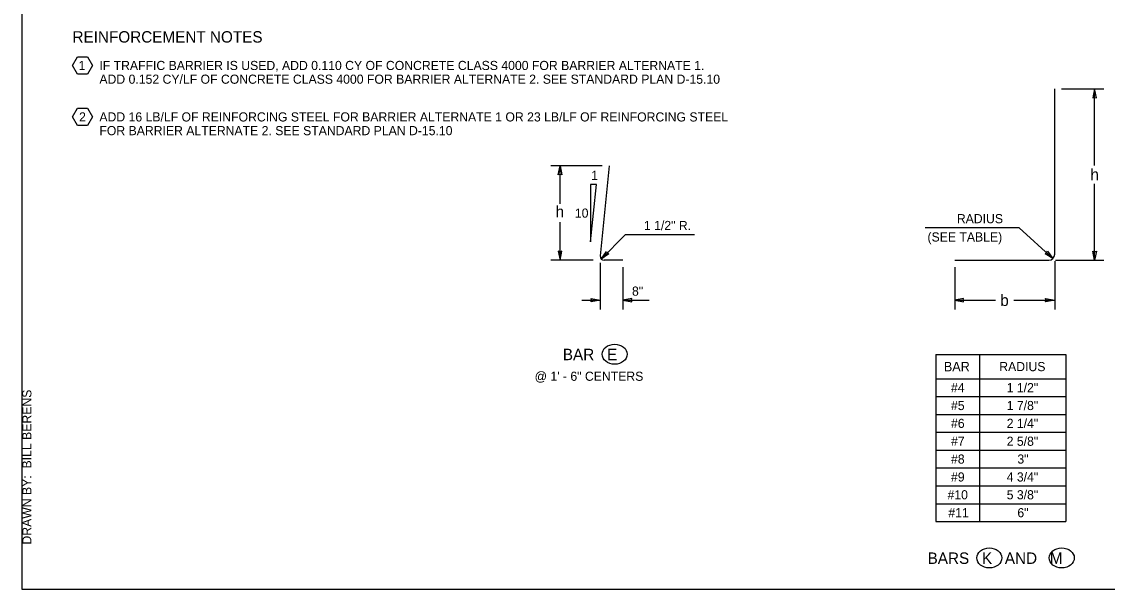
# Model space of a CAD drawing. Extents: x 99862 to 103151, y 100000 to 105076.
# Drawn here: x 99862 to 101763, y 103000 to 103992 of the extents above; entities that cross this region are included whole.
import ezdxf

# ---------------------------------------------------------------- set-up
doc = ezdxf.new("R2010")
doc.units = 0
for name, color, linetype in [('Level 1', 7, 'Continuous'), ('Level 15', 7, 'Continuous'), ('Level 20', 7, 'Continuous'), ('Level 21', 7, 'Continuous'), ('Level 4', 7, 'Continuous'), ('Level 5', 7, 'Continuous'), ('Level 60', 7, 'Continuous'), ('Level 62', 7, 'Continuous')]:
    doc.layers.add(name, color=color, linetype=linetype)

msp = doc.modelspace()

# ---------------------------------------------------------------- linework, layer by layer
at = {"layer": 'Level 1'}
msp.add_lwpolyline([(99862, 102999.5), (103151, 102999.5), (103151, 105075.5), (99862, 105075.5)], close=True, dxfattribs=at)
at = {"layer": 'Level 15'}
for p, q in [((101682.7, 103875.1), (101756.7, 103875.1)), ((101740.7, 103741.1), (101740.7, 103875.1)), ((100878.3, 103740.1), (100788.6, 103740.1)), ((100804.6, 103673.6), (100804.6, 103740.1)), ((100868.2, 103707.6), (100858.2, 103707.6)), ((100858.2, 103707.6), (100858.2, 103607.6)), ((100858.2, 103607.6), (100868.2, 103707.6)), ((101740.7, 103575.1), (101740.7, 103709.1)), ((100804.6, 103575.1), (100804.6, 103641.6)), ((100919.5, 103620), (100876.8, 103577.3)), ((100919.5, 103620), (101040.1, 103620)), ((101608.3, 103631.9), (101444.2, 103631.9)), ((101608.3, 103631.9), (101667.6, 103578.2)), ((100862.6, 103575.1), (100788.6, 103575.1)), ((100874.6, 103570.6), (100874.6, 103489.1)), ((100914.6, 103563.1), (100914.6, 103489.1)), ((101495.6, 103563.1), (101495.6, 103489.1)), ((101670.7, 103573.6), (101670.7, 103489.1)), ((101672.2, 103575.1), (101756.7, 103575.1)), ((100842.6, 103505.1), (100874.6, 103505.1)), ((100914.6, 103505.1), (100960.4, 103505.1)), ((101495.6, 103505.1), (101567.1, 103505.1)), ((101599.1, 103505.1), (101670.7, 103505.1))]:
    msp.add_line(p, q, dxfattribs=at)
for points in [[(101740.7, 103875.1), (101737.6, 103859.4), (101740.7, 103860.1), (101743.8, 103859.4)], [(101740.7, 103875.1), (101739.1, 103867.3), (101740.7, 103867.6), (101742.2, 103867.3)], [(100804.6, 103740.1), (100807.7, 103724.4), (100804.6, 103725.1), (100801.5, 103724.4)], [(100804.6, 103575.1), (100807.7, 103590.9), (100804.6, 103590.1), (100801.5, 103590.9)], [(100876.8, 103577.3), (100885.8, 103590.6), (100887.4, 103587.9), (100890.1, 103586.3)], [(101667.6, 103578.2), (101653.9, 103586.5), (101656.5, 103588.3), (101658, 103591)], [(101740.7, 103575.1), (101737.6, 103590.9), (101740.7, 103590.1), (101743.8, 103590.9)], [(101740.7, 103575.1), (101739.1, 103583), (101740.7, 103582.6), (101742.2, 103583)], [(100874.6, 103505.1), (100858.9, 103502.1), (100859.6, 103505.1), (100858.9, 103508.2)], [(100914.6, 103505.1), (100930.3, 103502.1), (100929.6, 103505.1), (100930.3, 103508.2)], [(101495.6, 103505.1), (101511.3, 103502.1), (101510.6, 103505.1), (101511.3, 103508.2)], [(101670.7, 103505.1), (101654.9, 103502.1), (101655.7, 103505.1), (101654.9, 103508.2)]]:
    msp.add_lwpolyline(points, close=True, dxfattribs=at)
at = {"layer": 'Level 20'}
for points in [[(99951.2, 103915.9), (99959.8, 103930.9), (99977.1, 103930.9), (99985.8, 103915.9), (99977.1, 103900.9), (99959.8, 103900.9), (99951.2, 103915.9)], [(99951.2, 103825.9), (99959.8, 103840.9), (99977.1, 103840.9), (99985.8, 103825.9), (99977.1, 103810.9), (99959.8, 103810.9), (99951.2, 103825.9)]]:
    msp.add_lwpolyline(points, dxfattribs=at)
for centre in [(100900.2, 103410.7), (101556.3, 103054.3), (101683.2, 103054.3)]:
    msp.add_ellipse(centre, major_axis=(-21.9, 0), ratio=0.8, dxfattribs=at)
at = {"layer": 'Level 4'}
for p, q in [((101462.5, 103410.3), (101690.5, 103410.3)), ((101462.5, 103410.3), (101462.5, 103117.9)), ((101539.1, 103410.3), (101539.1, 103117.9)), ((101690.5, 103410.3), (101690.5, 103117.9)), ((101462.5, 103367.9), (101690.5, 103367.9)), ((101462.5, 103336.7), (101690.5, 103336.7)), ((101462.5, 103305.4), (101690.5, 103305.4)), ((101462.5, 103274.2), (101690.5, 103274.2)), ((101462.5, 103242.9), (101690.5, 103242.9)), ((101462.5, 103211.7), (101690.5, 103211.7)), ((101462.5, 103180.4), (101690.5, 103180.4)), ((101462.5, 103149.2), (101690.5, 103149.2)), ((101462.5, 103117.9), (101690.5, 103117.9))]:
    msp.add_line(p, q, dxfattribs=at)
at = {"layer": 'Level 5'}
for p, q in [((101670.7, 103585.6), (101670.7, 103875.1)), ((100890.4, 103740.1), (100874.6, 103582.6)), ((100914.6, 103575.1), (100882.1, 103575.1)), ((101495.6, 103575.1), (101660.2, 103575.1))]:
    msp.add_line(p, q, dxfattribs=at)
for centre, radius, start, end in [((100882.1, 103582.6), 7.5, 180, 270), ((101660.2, 103585.6), 10.5, 270, 0)]:
    msp.add_arc(centre, radius, start, end, dxfattribs=at)
at = {"layer": 'Level 60'}
msp.add_line((99862, 102999.5), (99862, 102999.5), dxfattribs=at)

# ---------------------------------------------------------------- texts
at = {"layer": 'Level 20'}
for s, height, p in [('1', 16, (99961.6, 103907.9)), ('2', 16, (99962.5, 103817.9)), ('1', 16, (100859.1, 103715.6)), ('10', 16, (100830.6, 103649.6)), ('RADIUS', 16, (101499.4, 103639.9)), ('(SEE TABLE)', 16, (101448, 103607.9)), ('8"', 16, (100930.6, 103513.1)), ('b', 20, (101575.4, 103495.1)), ('BAR   E', 20, (100809.5, 103400.3)), ('BARS   K   AND   M', 20, (101448.2, 103043.9))]:
    msp.add_text(s, height=height, dxfattribs=at).set_placement(p)
for s, height, rotation, p in [('h', 20, 360, (101733.3, 103715.1)), ('h', 20, 360, (100796.8, 103650)), ('1 1/2" R.', 16, 359.9128, (100951.5, 103628))]:
    msp.add_text(s, height=height, rotation=rotation, dxfattribs=at).set_placement(p)
at = {"layer": 'Level 21'}
msp.add_text('@ 1\' - 6" CENTERS', height=16, dxfattribs=at).set_placement((100760.1, 103364.2))
at = {"layer": 'Level 4'}
for s, height, p in [('REINFORCEMENT NOTES', 20, (99950.9, 103955.9)), ('IF TRAFFIC BARRIER IS USED, ADD 0.110 CY OF CONCRETE CLASS 4000 FOR BARRIER ALTERNATE 1. ', 16, (99998, 103907.9)), ('ADD 0.152 CY/LF OF CONCRETE CLASS 4000 FOR BARRIER ALTERNATE 2. SEE STANDARD PLAN D-15.10', 16, (99998, 103883.9)), ('ADD 16 LB/LF OF REINFORCING STEEL FOR BARRIER ALTERNATE 1 OR 23 LB/LF OF REINFORCING STEEL', 16, (99998, 103817.9)), ('FOR BARRIER ALTERNATE 2. SEE STANDARD PLAN D-15.10', 16, (99998, 103793.9)), ('BAR', 16.5, (101476.7, 103380.8)), ('RADIUS', 16, (101573.7, 103381.1)), ('#4', 16, (101489.2, 103344.3)), ('1 1/2"', 16, (101586.7, 103344.3)), ('1 7/8"', 16, (101586.7, 103313)), ('#5', 16, (101489.2, 103313)), ('#6', 16, (101489.2, 103281.8)), ('2 1/4"', 16, (101586.7, 103281.8)), ('#7', 16, (101489.3, 103250.5)), ('2 5/8"', 16, (101586.7, 103250.5)), ('#8', 16, (101489.2, 103219.3)), ('3"', 16, (101605.4, 103219.3)), ('#9', 16, (101489.2, 103188)), ('4 3/4"', 16, (101586.7, 103188)), ('#10', 16, (101483.1, 103156.8)), ('5 3/8"', 16, (101586.7, 103156.8)), ('#11', 16, (101484.6, 103125.5)), ('6"', 16, (101605.4, 103125.5))]:
    msp.add_text(s, height=height, dxfattribs=at).set_placement(p)
at = {"layer": 'Level 62'}
msp.add_text('DRAWN BY:  BILL BERENS', height=16, rotation=90, dxfattribs=at).set_placement((99879, 103077.7))

doc.saveas('drawing.dxf')
